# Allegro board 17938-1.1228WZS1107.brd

Outline 227 x 153 mm; copper layers: TOP, L2SGND, L3, L4, L5SGND, BOTTOM. Coordinates in mm from the lower left corner of the outline.

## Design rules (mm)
constraint set DEFAULT: min track width 0.127, pair gap 0.102
net group CFG: nets CFG3 CFG4
net group CNVI_CLK: nets CLKIN_XTAL_LCP PULSAR_38P4M_REFCLK
net group DDR4_A_BA_40-MW: nets M_A_BA0 M_A_BA1
net group DDR4_A_BG_40-MW: nets M_A_BG0 M_A_BG1
net group DDR4_B_BA_40-MW: nets M_B_BA0 M_B_BA1
net group DDR4_B_BG_40-MW: nets M_B_BG0 M_B_BG1
net group DDR4_RST_40: nets DDR4_DRAMRST# SM_DRAMRST#_CPU
net group EMMC: nets EMMC_RESET# EMMC_RST_N
net group ESPI_IO0: nets ESPI_IO0 PCH_ESPI_IO0
net group ESPI_IO1: nets ESPI_IO1 PCH_ESPI_IO1
net group ESPI_IO2: nets ESPI_IO2 PCH_ESPI_IO2
net group ESPI_IO3: nets ESPI_IO3 PCH_ESPI_IO3
net group LED_5MIL: nets AMBER_LED_BAT WHITE_LED_BAT
net group MEM_SMBCLK: nets MEM_SMBCLK PCH_SMBCLK
net group MEM_SMBDATA: nets MEM_SMBDATA PCH_SMBDATA
net group ODD_SATA_RX_CON_N: nets ODD_SATA_RX_N12 SSD_ODD_SATA_RX_N12
net group ODD_SATA_RX_CON_P: nets ODD_SATA_RX_P12 SSD_ODD_SATA_RX_P12
net group ODD_SATA_TX_CON_N: nets ODD_SATA_TX_N12 SSD_ODD_SATA_TX_N12
net group ODD_SATA_TX_CON_P: nets ODD_SATA_TX_P12 SSD_ODD_SATA_TX_P12
net group SPI_HOLD_CPU: nets SPI_HOLD_CPU_R SPI_HOLD_ROM2
net group SPI_WP_CPU: nets SPI_WP_CPU_R SPI_WP_ROM2
net group T8-MW: nets CMP_VIN0 CMP_VIN0_R
net group THERM_SHUTDOWN: nets PURE_HW_SHUTDOWN# THERM_SYS_SHDN#
net group USB4_USB20_CON_N: nets USB4_USB20_CON_N USB4_USB20_N
net group USB4_USB20_CON_P: nets USB4_USB20_CON_P USB4_USB20_P
net group WWAN_USB20_N: nets WWAN_USB20_N WWAN_USB20_N_R
net group WWAN_USB20_P: nets WWAN_USB20_P WWAN_USB20_P_R
net group 00_POWER_4M: nets ACOK_IN_M PSID_DISABLE#_R_C PWR_1D05V_TON PWR_1D8V_EN PWR_1D8V_PG PWR_3D3V_EN PWR_3D3V_EN1 PWR_5V_EN
net group 00_POWER_10M: nets 1D0V_VCCA_XTAL 1D0V_VCCAMPHYPLL 1D0V_VCCDSW 1D8V_S0_CT1 1V_VCCSTG 3D3V_LAN_CT2 3V5V_CT1 3V5V_CT2 CEXT DC_IN_OFF FP_3D3V I_BATT LDO1_CAP LDO2_CAP LDO3_CAP LOM_TCT LPS_SW LPS_SW_A LPS_SW_C LPS_SW_D MESW1_B MIC_CAP NXP3290CAP PD_VBUS_DISCHG_N1 PD_VCCD PS_ID PU4348_G RSET SM_PGCNTL V3D3_STB VCCRTCEXT VDDI
net group 00_POWER_10M_10M: nets PWR_CHG_PHASE2_R
net group 00_POWER_10M_POWER: nets 3D3V_GSEN2 3D3V_MUX 3D3V_MUX2 3D3V_MUX_VCC AC_IN#_G AD_OFF_L AD_OFF_R PWR_1D05V_EN PWR_1D05V_PFM# PWR_1D05V_SS PWR_2D5V_EN PWR_5V_EN1 PWR_5V_VOUT PWR_CHG_ACIN PWR_CHG_ADP/ACIN PWR_CHG_AIN PWR_CHG_AIN_R PWR_CHG_AMON PWR_CHG_ASGATE PWR_CHG_ASGATE/NTC PWR_CHG_BATGONE PWR_CHG_CMRSC PWR_CHG_COMP PWR_CHG_COMP_R PWR_CHG_DCIN PWR_CHG_DCIN_R PWR_CHG_NTC PWR_CHG_OTGEN PWR_CHG_OTGPG PWR_CHG_PROG PWR_CHG_VBAT1 PWR_VCCGT_COMP PWR_VCCGT_COMP1 PWR_VCCGT_FCCM# PWR_VCCGT_FCCM#_RA PWR_VCCGT_FCCM#_RB PWR_VCCGT_IMON PWR_VCCGT_ISEN1 PWR_VCCGT_ISEN2 PWR_VCCGT_ISUMN PWR_VCCGT_ISUMN_P_1 PWR_VCCGT_ISUMN_P_2 PWR_VCCGT_ISUMN_RC PWR_VCCGT_ISUMNB PWR_VCCGT_ISUMP PWR_VCCGT_NTC PWR_VCCGT_NTC1 PWR_VCCGT_PWMA PWR_VCCGT_PWMA_RA PWR_VCCGT_PWMB PWR_VCCGT_PWMB_RA PWR_VCCGT_RTN PWR_VCCSA_COMP PWR_VCCSA_COMP_RC PWR_VCCSA_FCCM PWR_VCCSA_IMON PWR_VCCSA_ISUMN PWR_VCCSA_ISUMN_P_1 PWR_VCCSA_ISUMN_P_2 PWR_VCCSA_ISUMN_RC PWR_VCCSA_ISUMNB PWR_VCCSA_ISUMP PWR_VCCSA_PWM PWR_VCCSA_RTN PWR_VCORE_COMP PWR_VCORE_COMP1 PWR_VCORE_FCCM# PWR_VCORE_FCCM#_R PWR_VCORE_IMON PWR_VCORE_ISUMN PWR_VCORE_ISUMN_P_1 PWR_VCORE_ISUMN_P_2 PWR_VCORE_ISUMN_RC PWR_VCORE_ISUMNA PWR_VCORE_ISUMP PWR_VCORE_NTC PWR_VCORE_NTC1 PWR_VCORE_PROG1 PWR_VCORE_PROG2 PWR_VCORE_PWM PWR_VCORE_PWM_R PWR_VCORE_RTN PWR_VCORE_VR PWR_VCORE_VRHOT# PWR_VDDQ_CS PWR_VDDQ_EN PWR_VDDQ_PG PWR_VDDQ_TON PWR_VDDQ_VTTREF VDD
net group 00_POWER_15M: nets Q6205_Q USBC1_CC1_CONN USBC1_CC2_CONN
net group 00_POWER_15M_20M: nets PWR_1D05V_FB PWR_1D05V_FB_A PWR_1D8V_FB PWR_2D5V_FB PWR_3D3V_FB PWR_5V_FB PWR_5V_FB_A PWR_VCCGT_FB PWR_VCCGT_FB1 PWR_VCCGT_FB2 PWR_VCCGT_FB_RC PWR_VCCSA_FB PWR_VCCSA_FB1 PWR_VCCSA_FB2 PWR_VCCSA_FB_RC PWR_VCORE_FB PWR_VCORE_FB1 PWR_VCORE_FB2 PWR_VCORE_FB_RC PWR_VDDQ_FB
net group 00_POWER_20M: nets 1D8V_AVDD2 1D8V_EMMC 1D24V_VCCDPHY_EC 3D3V_AUX_S5 3D3V_RTC 3D3V_RTC_SYS 3D3V_SPIVCC1 3D3V_VCCPRTC 5V_HDMI 5V_IRLED 5V_VCONN_P1 5V_VCONN_P1_CCG4 +5V_AVDD +5V_KB_BL +RTC_CELL_VBAT +RTC_VCC +V_VREF_PATH1 CPVDD VDD10 VREF_CPU
net group 00_POWER_20M_20M: nets PWR_1D05V_BST PWR_CHG_BGATE PWR_CHG_BOOT1 PWR_CHG_BOOT2 PWR_CHG_BT1_R PWR_CHG_BT2_R PWR_VCCGT_BOOTA PWR_VCCGT_BOOTA_RC PWR_VCCGT_BOOTB PWR_VCCGT_BOOTB_RC PWR_VCCGT_BOOTRA PWR_VCCGT_BOOTRB PWR_VCCGT_SNB1 PWR_VCCGT_SNB2 PWR_VCCGT_VCCDA PWR_VCCGT_VCCDB PWR_VCCSA_BST PWR_VCCSA_BST_RC PWR_VCORE_BOOT PWR_VCORE_BOOT_RC PWR_VCORE_BOOTR PWR_VCORE_SNB PWR_VDDQ_BOOT PWR_VDDQ_BOOTA
net group 00_POWER_20M_POWER: nets PWR_3D3V_BOOT PWR_3D3V_BOOT_A PWR_5V_BOOT PWR_5V_BOOT_A PWR_5V_LDO PWR_CHG_BGATE/HG2 PWR_CHG_BGATE_22 PWR_CHG_BGATE_22_R PWR_CHG_NGATE PWR_CHG_VDDP PWR_VCORE_VCC PWR_VCORE_VCC_R PWR_VCORE_VIN
net group 00_POWER_25M_20M: nets PQ3802_1
net group 00_POWER_30M_10M: nets PWR_CHG_UGATE1
net group 00_POWER_40M: nets 3D3V_CAMERA_S0 3D3V_S5_PCH_R +1.8VALW_EC PQ4348_D
net group 00_POWER_80M: nets 3D3V_LCDVDD_R
net group 00_POWER_100M: nets 5V_AUX_S5
net group 00_POWER_320M_POWER: nets PWR_3D3V_VOUT
net group ASYNCHRONOUS: nets H_CPUPWRGD PROCHOT#_CPU_R PWR_CHG_PROCHOT# PWR_CHG_PROCHOT#_R THERMTRIP#_CPU VCCST_PWRGD_R VDDQ_PWRGD VR_EN XDP_DBRESET#
net group AUDIO_12MIL: nets CPVEE
net group AUDIO_BEEP_10MIL: nets AUD_HPJD_N AUD_PC_BEEP AUD_PC_BEEP_C AUD_SENSE AUD_VREF BEEP CBN CBP HDA_SPKR_R JACK_PLUG JACK_PLUG_DET KBC_BEEP_R LINE1_VREFO LINE1_VREFO_D1 LINE1_VREFO_D2 MIC2_VREFO SPKR
net group AUDIO_BEEP_15MIL: nets AUD_PORTA_L_HPMIC1 AUD_PORTA_R_HPMIC1 LINE1-L_C LINE1-L_R LINE1_L LINE1_R
net group AUDIO_DIGITAL_50-MWS: nets HDA_RST_N_CPU
net group AUDIO_JACK_15MIL: nets AUD_HP1_JACK_L AUD_HP1_JACK_L1 AUD_HP1_JACK_R
net group AUDIO_SLEEVE_40MIL: nets SLEEVE_R
net group BOT_MUX_N: nets USB1_USB20_N
net group BOT_MUX_P: nets USB1_USB20_P
net group BT_USB20_CON_N: nets BT_USB20_N
net group BT_USB20_CON_P: nets BT_USB20_P
net group CARD1_USB20_CON_N: nets CARD1_USB20_N
net group CARD1_USB20_CON_P: nets CARD1_USB20_P
net group CCD_USB20_CON_N: nets CCD_USB20_N
net group CCD_USB20_CON_P: nets CCD_USB20_P
net group CLK_50: nets PD_SWD_CLK SUS_CLK SUSACK#_R SUSCLK_WLAN
net group CLK_ITE8010: nets CLK_ITE8010 CPU_SMB_SCL_THM GPU_THM_SMBCLK SML1_SMBCLK
net group CNV_BRI_DT: nets CNV_BRI_DT
net group CNV_BRI_RSP: nets CNV_BRI_RSP
net group CNV_RGI_DT: nets CNV_RGI_DT
net group CNV_RGI_RSP: nets CNV_RGI_RSP
net group CNVI_RCOMP: nets CNV_WT_RCOMP
net group COMP_20MIL: nets CFG_RCOMP CPU_POPIRCOMP PCH_POPIRCOMP SM_RCOMP_0 SM_RCOMP_1 SM_RCOMP_2
net group CPU_50-MWS: nets CMP_VOUT0
net group CPU_DP1_CTRL_CLK: nets CPU_DP1_CTRL_CLK
net group CPU_DP1_CTRL_DATA: nets CPU_DP1_CTRL_DATA
net group CPU_SMB_SDA_THM: nets CPU_SMB_SDA_THM DAT_ITE8010 GPU_THM_SMBDAT SML1_SMBDATA
net group CRITICAL: nets PCH_RSMRST# PM_RSMRST# PM_RSMRST#_M RESET_OUT# RTC_RST# SIO_PWRBTN# SIO_RCIN# SM_INTRUDER# SRTC_RST# SYS_PWROK
net group CRT_AUX_CPU_N: nets DP2_AUX_C_N DP2_AUX_CPU_N IN_AUX_N TYPEC_DP_AUXN
net group CRT_AUX_CPU_P: nets DP2_AUX_C_P DP2_AUX_CPU_P IN_AUX_P TYPEC_DP_AUXP
net group CRT_DDI_TX_N0: nets CRT_DDI_TX_N0 DP2_DDI_TX_N0 DP2_DDI_TX_R_N0 DP2_DDI_TX_R_N0_R DP2_DDI_TX_RE_C_N0 DP2_DEMUX_OUT2_D0N TYPEC_DP_N0 TYPEC_DP_N0_C
net group CRT_DDI_TX_N1: nets CRT_DDI_TX_N1 DP2_DDI_TX_N1 DP2_DDI_TX_R_N1 DP2_DDI_TX_R_N1_R DP2_DDI_TX_RE_C_N1 DP2_DEMUX_OUT2_D1N TYPEC_DP_N1 TYPEC_DP_N1_C
net group CRT_DDI_TX_P0: nets CRT_DDI_TX_P0 DP2_DDI_TX_P0 DP2_DDI_TX_R_P0 DP2_DDI_TX_R_P0_R DP2_DDI_TX_RE_C_P0 DP2_DEMUX_OUT2_D0P TYPEC_DP_P0 TYPEC_DP_P0_C
net group CRT_DDI_TX_P1: nets CRT_DDI_TX_P1 DP2_DDI_TX_P1 DP2_DDI_TX_R_P1 DP2_DDI_TX_R_P1_R DP2_DDI_TX_RE_C_P1 DP2_DEMUX_OUT2_D1P TYPEC_DP_P1 TYPEC_DP_P1_C
net group DDR4_A_CKE_40-MW: nets M_A_CKE0 M_A_CKE1 M_A_CS#0 M_A_CS#1 M_A_DIMA_ODT0 M_A_DIMA_ODT1
net group DDR4_A_CMD_40-MW: nets M_A_A0 M_A_A1 M_A_A2 M_A_A3 M_A_A4 M_A_A5 M_A_A6 M_A_A7 M_A_A8 M_A_A9 M_A_A10 M_A_A11 M_A_A12 M_A_A13 M_A_A14 M_A_A15 M_A_A16 M_A_ACT_N M_A_ALERT_N M_A_PARITY
net group DDR4_A_DATA_00_50-MW: nets M_A_DQ0 M_A_DQ1 M_A_DQ2 M_A_DQ3 M_A_DQ4 M_A_DQ5 M_A_DQ6 M_A_DQ7
net group DDR4_A_DATA_01_50-MW: nets M_A_DQ8 M_A_DQ9 M_A_DQ10 M_A_DQ11 M_A_DQ12 M_A_DQ13 M_A_DQ14 M_A_DQ15
net group DDR4_A_DATA_02_50-MW: nets M_A_DQ16 M_A_DQ17 M_A_DQ18 M_A_DQ19 M_A_DQ20 M_A_DQ21 M_A_DQ22 M_A_DQ23
net group DDR4_A_DATA_03_50-MW: nets M_A_DQ24 M_A_DQ25 M_A_DQ26 M_A_DQ27 M_A_DQ28 M_A_DQ29 M_A_DQ30 M_A_DQ31
net group DDR4_A_DATA_04_50--MW: nets M_A_DQ32 M_A_DQ33 M_A_DQ34 M_A_DQ35 M_A_DQ36 M_A_DQ37 M_A_DQ38 M_A_DQ39
net group DDR4_A_DATA_05_50-MW: nets M_A_DQ40 M_A_DQ41 M_A_DQ42 M_A_DQ43 M_A_DQ44 M_A_DQ45 M_A_DQ46 M_A_DQ47
net group DDR4_A_DATA_06_50-MW: nets M_A_DQ48 M_A_DQ49 M_A_DQ50 M_A_DQ51 M_A_DQ52 M_A_DQ53 M_A_DQ54 M_A_DQ55
net group DDR4_A_DATA_07_50-MW: nets M_A_DQ56 M_A_DQ57 M_A_DQ58 M_A_DQ59 M_A_DQ60 M_A_DQ61 M_A_DQ62 M_A_DQ63
net group DDR4_B_CKE_40-MW: nets M_B_CKE0 M_B_CKE1 M_B_CS#0 M_B_CS#1 M_B_DIMB_ODT0 M_B_DIMB_ODT1
net group DDR4_B_CMD_40--MW: nets M_B_A0 M_B_A1 M_B_A2 M_B_A3 M_B_A4 M_B_A5 M_B_A6 M_B_A7 M_B_A8 M_B_A9 M_B_A10 M_B_A11 M_B_A12 M_B_A13 M_B_A14 M_B_A15 M_B_A16 M_B_ACT_N M_B_ALERT_N M_B_PARITY
net group DDR4_B_DATA_00_50-MW: nets M_B_DQ0 M_B_DQ1 M_B_DQ2 M_B_DQ3 M_B_DQ4 M_B_DQ5 M_B_DQ6 M_B_DQ7
net group DDR4_B_DATA_01_50-MW: nets M_B_DQ8 M_B_DQ9 M_B_DQ10 M_B_DQ11 M_B_DQ12 M_B_DQ13 M_B_DQ14 M_B_DQ15
net group DDR4_B_DATA_02_50-MW: nets M_B_DQ16 M_B_DQ17 M_B_DQ18 M_B_DQ19 M_B_DQ20 M_B_DQ21 M_B_DQ22 M_B_DQ23
net group DDR4_B_DATA_03_50-MW: nets M_B_DQ24 M_B_DQ25 M_B_DQ26 M_B_DQ27 M_B_DQ28 M_B_DQ29 M_B_DQ30 M_B_DQ31
net group DDR4_B_DATA_04_50-MW: nets M_B_DQ32 M_B_DQ33 M_B_DQ34 M_B_DQ35 M_B_DQ36 M_B_DQ37 M_B_DQ38 M_B_DQ39
net group DDR4_B_DATA_05_50-MW: nets M_B_DQ40 M_B_DQ41 M_B_DQ42 M_B_DQ43 M_B_DQ44 M_B_DQ45 M_B_DQ46 M_B_DQ47
net group DDR4_B_DATA_06_50-MW: nets M_B_DQ48 M_B_DQ49 M_B_DQ50 M_B_DQ51 M_B_DQ52 M_B_DQ53 M_B_DQ54 M_B_DQ55
net group DDR4_B_DATA_07_50-MW: nets M_B_DQ56 M_B_DQ57 M_B_DQ58 M_B_DQ59 M_B_DQ60 M_B_DQ61 M_B_DQ62 M_B_DQ63
net group DDR4_VREF_40: nets V_SM_VREF_CNTB
net group DMIC: nets DMIC_CLK_EDP DMIC_DATA_EDP DMIC_SCL_CODEC DMIC_SCL_CODEC_R DMIC_SDA_CODEC
net group DP2_DDI_TX_C_N2: nets DP2_DDI_TX_C_N2_R DP2_DDI_TX_RE_C_N2 TYPEC_DP_N2 TYPEC_DP_N2_C
net group DP2_DDI_TX_C_N3: nets DP2_DDI_TX_C_N3_R DP2_DDI_TX_RE_C_N3 TYPEC_DP_N3 TYPEC_DP_N3_C
net group DP2_DDI_TX_C_P2: nets DP2_DDI_TX_C_P2_R DP2_DDI_TX_RE_C_P2 TYPEC_DP_P2 TYPEC_DP_P2_C
net group DP2_DDI_TX_C_P3: nets DP2_DDI_TX_C_P3_R DP2_DDI_TX_RE_C_P3 TYPEC_DP_P3 TYPEC_DP_P3_C
net group E3: nets 3D3V_LCDVDD_R_C 3D3V_LCDVDD_S0_C 3D3V_S0_C 3D3V_SSD_C BT_PWR_IN+ BT_PWR_IN- DCBATOUT_C1 DCBATOUT_C6 DCBATOUT_C7 DCBATOUT_C8 DCBATOUT_LCD_C DCBATOUT_LCD_R_C PWR_DCBATOUT_VCCGTA_C PWR_DCBATOUT_VCCSA_C PWR_DCBATOUT_VCORE_C PWR_DCBATOUT_VDDQ_C
net group EDP_AUX_CON_N: nets EDP_AUX_CPU_N
net group EDP_AUX_CON_P: nets EDP_AUX_CPU_P
net group EDP_RCOMP: nets EDP_RCOMP_CPU
net group EDP_TX_CON_N0: nets EDP_TX_CPU_N0
net group EDP_TX_CON_N1: nets EDP_TX_CPU_N1
net group EDP_TX_CON_P0: nets EDP_TX_CPU_P0
net group EDP_TX_CON_P1: nets EDP_TX_CPU_P1
net group EMMC_CLK: nets EMMC_CLK
net group EMMC_CMD: nets EMMC_CMD
net group EMMC_D0: nets EMMC_D0
net group EMMC_D1: nets EMMC_D1
net group EMMC_D2: nets EMMC_D2
net group EMMC_D3: nets EMMC_D3
net group EMMC_D4: nets EMMC_D4
net group EMMC_D5: nets EMMC_D5
net group EMMC_D6: nets EMMC_D6
net group EMMC_D7: nets EMMC_D7
net group EMMC_RCLK: nets EMMC_RCLK
net group EMMC_RCOMP: nets SD_RCOMP
net group EPSI_50: nets ESPI_ALERT#
net group ESPI_CLK: nets PCH_ESPI_CLK
net group FAN_TACH: nets FAN1_TACH FAN_TACH1 FAN_TACH1_C
net group FP1_USB20_CON_N: nets FP1_USB20_N
net group FP1_USB20_CON_P: nets FP1_USB20_P
net group GND: nets U9101_2_GND
net group HDD2_SATA_RX_CON_N: nets HDD_SATA_RX_N11
net group HDD2_SATA_RX_CON_P: nets HDD_SATA_RX_P11
net group HDD2_SATA_TX_CON_N: nets HDD_SATA_TX_N11
net group HDD2_SATA_TX_CON_P: nets HDD_SATA_TX_P11
net group HDMI_DDI_TX_CMC_N0: nets HDMI_DDI_TX_N2
net group HDMI_DDI_TX_CMC_N1: nets HDMI_DDI_TX_N1
net group HDMI_DDI_TX_CMC_N2: nets HDMI_DDI_TX_N0
net group HDMI_DDI_TX_CMC_N3: nets HDMI_DDI_TX_N3
net group HDMI_DDI_TX_CMC_P0: nets HDMI_DDI_TX_P2
net group HDMI_DDI_TX_CMC_P1: nets HDMI_DDI_TX_P1
net group HDMI_DDI_TX_CMC_P2: nets HDMI_DDI_TX_P0
net group HDMI_DDI_TX_CMC_P3: nets HDMI_DDI_TX_P3
net group JTAG-MW: nets PCH_JTAG_TCK PCH_JTAG_TDI PCH_JTAG_TDO PCH_JTAG_TMS
net group KB: nets KSI0 KSI1 KSI2 KSI3 KSI4 KSI5 KSI6 KSI7 KSO0 KSO1 KSO2 KSO3 KSO4 KSO5 KSO6 KSO7 KSO8 KSO9 KSO10 KSO11 KSO12 KSO13 KSO14 KSO15 KSO16
net group LAN_MDI0_N: nets MDO0-
net group LAN_MDI0_P: nets MDO0+
net group LAN_MDI1_N: nets MDO1-
net group LAN_MDI1_P: nets MDO1+
net group LAN_MDI2_N: nets MDO2-
net group LAN_MDI2_P: nets MDO2+
net group LAN_MDI3_N: nets MDO3-
net group LAN_MDI3_P: nets MDO3+
net group LAN_PCIE_RX_C_N: nets LAN_PCIE_RX_N
net group LAN_PCIE_RX_C_P: nets LAN_PCIE_RX_P
net group LED: nets BAT1_LED# BAT2_LED# BATT_WHITE_LED# BATT_WHITE_LED#_Q CAP_LED# CAP_LED#_R CHG_AMBER_LED# CHG_AMBER_LED#_Q M2_PCIE_LED# MASK_SATA_LED# PWR_LED# Q6407_B Q6407_C SATA_LED# SATA_LED#_D SYS_LED_MASK#
net group LED_8MIL: nets BAT_AMBER BAT_WHITE CAP_LED CAP_LED_Q LAN_LED0 LAN_LED0_Q LAN_LED0_R PWR_LED#_C PWR_LED#_R
net group OHTER_3D5MIL: nets 3V_5V_EN 3V_5V_POK AD_IA AUX_EN_WOWL AUX_EN_WOWL_R BLUETOOTH_EN BMON22 CAM_EN CLK_PCIE_LAN_REQ# CLK_PCIE_NVME_REQ# CLK_PCIE_WLAN_REQ# CNVI_EN# CPU_DP1_HPD CPU_DP_HPD_R CRT_DP_HPD_R DP2_HPD_CPU ESPI_CLK_CON ESPI_CS#_CON ESPI_IO0_CON ESPI_IO1_CON ESPI_IO2_CON ESPI_IO3_CON ESPI_RST#_CON FPR_SCAN# GPP_H1_SFRM GPP_H2_CLKREQ0 GPPC_H18_VCCIO_LPM HW_ACAV_IN IR_CAM_DET# KB_DET# KB_LED_BL_DET KBC_PWRBTN# L_BKLT_EN LAN_WAKE# LCD_CBL_DET# LCD_TST LCD_VCC_TEST_EN LID_CL_SIO# LID_CLOSE#_C M2_SSD_PEDET PANEL_BKEN PANEL_MONITOR PBAT_PRES# PCIE_WAKE# PD4403_K PLTRST#_CPU PQ4405_2 PQ4408_C PROCHOT#_CPU PTP_DIS# PWR_BD_DET# PWR_LED#_Q SIO_EXT_WAKE# SIO_SLP_S0# SIO_SLP_S4# SMB_ALERT# SSD_DEVSLP SSD_DEVSLP_R TOUCH_I2C_DET# TOUCH_PANEL_INTR# TP_EN# TP_WAKE_KBC# USB_EN# USB_OC0# USB_OC1# VGA_DB_DET# VRAM_ID1 VRAM_ID2 WIFI_RF_EN WWAN_BB_RST# WWAN_CLKREQ_CPU_N WWAN_DB_DET# WWAN_DB_DET#_R WWAN_GPIO_PERST# WWAN_PCIE_WAKE_N
net group OTHER_4MIL: nets 3D3V_CAMERA_CT1 3D3V_TP_CT2 3V_5V_POK# 5V_VCONN_EN 20V_VCCPD_VBUS_R +SDC_IN_SW_R1 ACOK# ALERT# AUX_ON BKLT_IN_EC BLON_OUT_C BLUETOOTH_EN_R BOARD_ID BOARD_ID1 BREATH_LED# BT_PCMFRM_RSTN BT_PCMOUT_CLKREQ0 C10_GATE CAD_SNK_MUX CCG4_FLIP# CCG4_I2C_INT# CCG4_ID_1 CFG0 CFG0_DP_MUX CFG1 CFG19 CHGR_PSYS_IMVP CLK_PCIE_SD_REQ# CPU_DP2_HPD CPU_DP_HPD_MUX CRT_DP_HPD CTL1 CTL2 CTL3 DBC_EN_R DBC_PANEL_EN DCBATOUT_LCD_PG DCBATOUT_LCD_PWRGD DOCK_USB_EN_A DOCK_USB_EN_B DPEQ0_A1 DPEQ1 EC_D_INHIB EDP_DISP_UTIL EDP_FHD_DET# EDP_FHD_DET#_R EDP_HPD EDP_HPD_CONN EQ0 EQ1 EXT_PWR_GATE# FALL_INT2 FFS_INT1 FFS_INT2 FFS_INT2_Q FLT_NXP3290 FP_EN# GPD11/LANPHYPC GPD_7 GPP_H21 GPP_H23 GSENSOR_CS GSENSOR_SDO HDD_DET# HDD_DEVSLP_R HDMI_HPD_B HDMI_HPD_CON HOST_DEBUG_TX HOST_DEBUG_TX_CON HPDIN HW_ACAV_IN0 HW_ACAVIN_NB0 I2C_CTL_EN I2CEN I_ADP IC_DELAY ICSP_CLR ILIM_HI ILIM_LO ILIM_SEL INPUT3VSEL INT#_ITE8010 IO_DB_DET# IO_DB_DET#_EC IO_DB_DET#_GPPG5 IO_DB_DET#_R ISOLATE# IST_TRIG ITP_PMODE JIO3_PCIE_WAKE# KB_BL_CTRL# KB_LED_DET_C KB_LED_PWM KBC_PWRBTN#_C L_BKLT_EN_L LAN_CABLE_DETECT_R_# LANWAKE# LCD_TST_C LCDVDD_EN LCDVDD_PG LCDVDD_PWRGD LOM_CABLE_DETECT# LPS_SW_R MCT0 MCT1 MCT2 MCT3 ME_FWP ME_FWP_R MODEL_ID MSATA_DEVSLP_R MUX_HPD_PD MUX_SAI MUX_SAO MUX_SBI MUX_SBO NB_MUTE# NRB_BIT NUVOTON_PP NXP3290_FO NXP3290_ILIM OUT1_CA_DET OUT2_CA_DET PANEL_BKEN_EC PANEL_PWRGD_R PBAT_PRES1# PC10 PC11 PC20 PC21 PCH_BATLOW# PCH_PLTRST# PCH_TPAN_VDD_EN PCH_WAKE# PCIE_LAN_WAKE# PD4403_A PD_VBUS_C_CTRL1_A PD_VBUS_C_CTRL1_R PD_VBUS_C_EN_A PD_VBUS_C_EN_B PD_XRES PDB_R PEQ PLTRST#_CPU_D PLTRST#_CPU_G PM_LAN_ENABLE POWER_SW_IN# PQ4405_3 PQ4405_5 PQ4405_6 PQ4408_E PQ4417_D PQ4417_G PQ4418_2 PQ4418_3 PQ4418_5 PQ4418_6 PRIM_PWRGD PROCHOT PROJECT_ID0 PROJECT_ID1 PROJECT_ID2 PROJECT_ID3 PS_ID_R PS_ID_R1 PWR_CHG_ACOK PWR_CHG_PSYS Q501_G Q2510_G Q5503_B Q5503_C Q5503_E Q5504_B Q5504_C Q5505_E Q9301_G REXT1 RTC_DET# RUNPWROK SA0_CHA_DIM0 SA0_CHB_DIM0 SA1_CHA_DIM0 SA1_CHB_DIM0 SA2_CHA_DIM0 SA2_CHB_DIM0 SATA1_ODD_PRSNT# SATA_ODD_DA#_C SATA_ODD_PRSNT#_R SD_READ_MODE# SD_READ_MODE#_R SIO_EXT_SMI# SIO_SLP_A# SIO_SLP_S3# SIO_SLP_S5# SM_PGCNTL_Q SSD2_DEVSLP SSD_SCP# SSEQ0_A0 SSEQ1 ST_GPIO ST_PP SW_PIN SYS_PRES1# SYSPWR_PRES T_CRIT# TOUCH_PAD_INTR# TOUCH_PANEL_PD# TOUCH_REPORT_SW TPAN_VDD_EN_R TPM_GPIO1 TPM_GPIO4 TPM_ID TPM_SPI_IRQ# TPS2544_FAULT# TPS70933_EN TPS70933_EN_G TS#_DIMM0_1 TS#_DIMM1_1 TS_INT# TYPEC_DCIN1_EN# USB2_ID USB2_VBUSSENSE USB_OC1#_R USB_OC2# USB_OC3# USB_PWR_SHR_EN_L# V0.85A_VID0 V0.85A_VID1 VBUS_P_CTRL VBUS_P_CTRL_R VCCDSW_ON VCCPD_VBUS_ACK VCCSTG_EN_R1 VCCSTU_EN_R VCI_IN1# VCREF0 VR_RDY VRALERT# WIFI_RF_EN_R WLAN_EN# WWAN_FULL_PWR_EN WWAN_FULL_PWR_EN_D8 WWAN_FULL_PWR_EN_R
net group PCIE_RCOMP: nets PCIE_RCOMPN PCIE_RCOMPP USBCOMP
net group PLATFORM: nets 1D05V_S5_PWRGD 3V_5V_DSW_OK AC_DIS AC_PRESENT ALWON CNVI_EN#_R EDP_VDD_EN GPP_E23_STRAP HDD_DEVSLP HW_ACAVIN_NB ME_SUS_PWR_ACK_R NC_AUX_EN_WOWL_EC PD_VBUS_C_CTRL1 PD_VBUS_DISCHG PIRQA# PWR_2D5V_PG RSMRST_PWRGD# RTC_3P3_EN_G RTCRST_ON TP_ON#_GATE TPM_GPIO0 USB_POWERSHARE_VBUS_EN
net group PWM: nets BKLT_CTRL FAN1_PWM FAN_PWM1_C L_BKLT_CTRL LCD_BRIGHTNESS
net group REF10M: nets VR_CAP
net group SIGNAL_SVID: nets SVID_ALERT#_CPU SVID_ALERT#_CPU_R SVID_ALERT#_VR SVID_CLK_CPU_R SVID_CLK_VR SVID_DATA_CPU_R SVID_DATA_VR
net group SIGNAL_V_F_5MIL: nets XCLK_BIASREF
net group SMBUS: nets CCG4_I2C_SCL CCG4_I2C_SDA CLK_TP_SIO CPU_DP2_CTRL_CLK CPU_DP2_CTRL_DATA DAT_TP_SIO DMIC_PCH_CLK DMIC_PCH_DATA HDMI_SCL_R HDMI_SDA_R I2C0_SCL_TCH_PAD I2C0_SCL_TCH_PNL I2C0_SDA_TCH_PAD I2C0_SDA_TCH_PNL I2C1_SCL_R I2C1_SDA_R I2C_CLK I2C_CLK_PD I2C_CLK_PD_MUX I2C_DATA_PD I2C_DATA_PD_MUX I2C_SDA ICSP_CLK ICSP_DAT PBAT_CHG_SMBCLK PBAT_CHG_SMBDAT PBAT_SMBCLK1 PBAT_SMBDAT1 PMBD_SCL_R PMBD_SDA_R SML0_ALERT# SML0_SMBCLK SML0_SMBDATA SML1ALERT# TPCLK_C TPDATA_C TYPEC_SMBCLK TYPEC_SMBDA
net group SPI_50-MWS: nets SPI_CS2#_IC SPI_CS_CPU_N0 SPI_CS_CPU_N1 SPI_CS_CPU_N2 SPI_IRQ#_TPM2
net group SPI_CLK_CPU: nets SPI_CLK_CPU_R SPI_CLK_ROM SPI_CLK_ROM2 SPI_CLK_ROM_TPM
net group SPI_SI_CPU: nets SPI_SI_CPU_R SPI_SI_ROM2 SPI_SI_ROM_TPM
net group SPI_SO_CPU: nets SPI_SO_CPU_R SPI_SO_ROM2 SPI_SO_ROM_TPM
net group SSD_PCIE_TX_CON_N13: nets SSD_PCIE_TX_N13
net group SSD_PCIE_TX_CON_N14: nets SSD_PCIE_TX_N14
net group SSD_PCIE_TX_CON_N15: nets SSD_PCIE_TX_N15
net group SSD_PCIE_TX_CON_P13: nets SSD_PCIE_TX_P13
net group SSD_PCIE_TX_CON_P14: nets SSD_PCIE_TX_P14
net group SSD_PCIE_TX_CON_P15: nets SSD_PCIE_TX_P15
net group SSD_PCIE_TX_N16: nets SSD_PCIE_TX_N16
net group SSD_PCIE_TX_P16: nets SSD_PCIE_TX_P16
net group SVID_PECI_THERMTRIP: nets H_PECI PECI_CPU SVID_CLK_CPU SVID_DATA_CPU
net group TOUCH_USB20_N: nets TOUCH_USB20_N
net group TOUCH_USB20_P: nets TOUCH_USB20_P
net group UART_MW-MW: nets UART_2_CRXD_DTXD UART_2_CRXD_DTXD_CON UART_2_CTXD_DRXD UART_2_CTXD_DRXD_CON
net group USB1_SSRX_CMC_N1: nets USB1_SSRX_C_N1
net group USB1_SSRX_CMC_N2: nets USB1_SSRX_C_N2
net group USB1_SSRX_CMC_P1: nets USB1_SSRX_C_P1
net group USB1_SSRX_CMC_P2: nets USB1_SSRX_C_P2
net group USB1_SSTX_CMC_N1: nets USB1_SSTX_C_N1
net group USB1_SSTX_CMC_N2: nets USB1_SSTX_C_N2
net group USB1_SSTX_CMC_P1: nets USB1_SSTX_C_P1
net group USB1_SSTX_CMC_P2: nets USB1_SSTX_C_P2
net group USB2_USB20_N: nets USB2_USB20_N
net group USB2_USB20_P: nets USB2_USB20_P
net group USB3_CHAR_2544_N: nets USB3_USB20_N
net group USB3_CHAR_2544_P: nets USB3_USB20_P
net group USB3_USB30_RX_CON_N: nets USB3_USB31_RX_N
net group USB3_USB30_RX_CON_P: nets USB3_USB31_RX_P
net group USB3_USB30_TX_CMC_N: nets USB3_USB31_TX_N
net group USB3_USB30_TX_CMC_P: nets USB3_USB31_TX_P
net group USB4_USB30_RX_C_N: nets USB4_USB30_RX_C_N USB4_USB30_RX_C_R_N USB4_USB30_RX_N
net group USB4_USB30_RX_C_P: nets USB4_USB30_RX_C_P USB4_USB30_RX_C_R_P USB4_USB30_RX_P
net group USB4_USB30_RX_CON_N: nets USB4_USB31_RX_N
net group USB4_USB30_RX_CON_P: nets USB4_USB31_RX_P
net group USB4_USB30_TX_C_N: nets USB4_USB30_TX_C_N USB4_USB30_TX_C_R_N USB4_USB30_TX_N
net group USB4_USB30_TX_C_P: nets USB4_USB30_TX_C_P USB4_USB30_TX_C_R_P USB4_USB30_TX_P
net group USB4_USB30_TX_CMC_N: nets USB4_USB31_TX_N
net group USB4_USB30_TX_CMC_P: nets USB4_USB31_TX_P
net group WWAN_PCIE_TX_N: nets WWAN_PCIE_TX_N
net group WWAN_PCIE_TX_P: nets WWAN_PCIE_TX_P
net group XDP: nets XDP_TCK_JTAGX XDP_TCLK XDP_TDI XDP_TDO_CPU XDP_TMS XDP_TRST#
net group XTAL-MW: nets LANXIN LANXOUT MEC_XTAL1_R MEC_XTAL2 XTL_32K_X1_CPU XTL_32K_X2_CPU
net group XTL_24M: nets XTL_24M_X1_CPU XTL_24M_X1_R XTL_24M_X2_CPU XTL_24M_X2_R
nets with their own width: min track width 0.381; nets GND

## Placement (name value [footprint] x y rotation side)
AFTP1201  AFTE14P-GP  [AFTE14P-75]  196.32 57.13 0 top
AFTP1202  AFTE14P-GP  [AFTE14P-75]  198.25 57.08 0 top
AFTP2601  AFTE14P-GP  [AFTE14P-75]  160.81 86.92 90 top
AFTP2602  AFTE14P-GP  [AFTE14P-75]  161.29 85.07 90 top
AFTP2603  AFTE14P-GP  [AFTE14P-75]  159.72 90.27 90 top
AFTP2604  AFTE14P-GP  [AFTE14P-75]  161.04 88.85 90 top
AFTP2901  AFTE14P-GP  [AFTE14P-75]  14.73 4.47 90 top
AFTP2902  AFTE14P-GP  [AFTE14P-75]  13.14 6.96 180 top
AFTP2903  AFTE14P-GP  [AFTE14P-75]  11.95 4.37 180 top
AFTP2904  AFTE14P-GP  [AFTE14P-75]  11.91 2.37 90 top
AFTP3201  AFTE14P-GP  [AFTE14P-75]  23.52 86.64 0 bottom
AFTP3202  AFTE14P-GP  [AFTE14P-75]  26.37 81.26 0 bottom
AFTP3204  AFTE14P-GP  [AFTE14P-75]  24.69 88.55 0 bottom
AFTP3205  AFTE14P-GP  [AFTE14P-75]  26.47 84.71 180 top
AFTP3206  AFTE14P-GP  [AFTE14P-75]  26.24 82.25 180 top
AFTP3207  AFTE14P-GP  [AFTE14P-75]  19.28 79.78 180 top
AFTP3208  AFTE14P-GP  [AFTE14P-75]  24.46 81.19 0 bottom
AFTP3209  AFTE14P-GP  [AFTE14P-75]  18.63 77.97 180 top
AFTP3502  AFTE14P-GP  [AFTE14P-75]  16.55 47.63 90 top
AFTP3503  AFTE14P-GP  [AFTE14P-75]  16.49 49.54 90 top
AFTP3505  AFTE14P-GP  [AFTE14P-75]  17.73 46.13 90 top
AFTP3506  AFTE14P-GP  [AFTE14P-75]  16.36 44.73 90 top
AFTP3507  AFTE14P-GP  [AFTE14P-75]  18.24 44.22 0 top
AFTP3508  AFTE14P-GP  [AFTE14P-75]  18.55 34.67 0 top
AFTP4001  AFTE14P-GP  [AFTE14P-75]  63.2 121.08 0 top
AFTP4002  AFTE14P-GP  [AFTE14P-75]  58.04 130.46 0 top
AFTP4003  AFTE14P-GP  [AFTE14P-75]  70.75 37.01 0 top
AFTP4302  AFTE14P-GP  [AFTE14P-75]  17.18 124.81 0 top
AFTP4303  AFTE14P-GP  [AFTE14P-75]  21.99 124.93 180 top
AFTP4304  AFTE14P-GP  [AFTE14P-75]  19.46 125.39 90 top
AFTP4306  AFTE14P-GP  [AFTE14P-75]  169.2 33.46 0 top
AFTP4307  AFTE14P-GP  [AFTE14P-75]  133.1 35.13 0 top
AFTP4308  AFTE14P-GP  [AFTE14P-75]  133.15 37.06 180 top
AFTP4309  AFTE14P-GP  [AFTE14P-75]  139.7 34.47 180 top
AFTP4310  AFTE14P-GP  [AFTE14P-75]  140.64 36.93 180 top
AFTP4311  AFTE14P-GP  [AFTE14P-75]  142.57 36.7 180 top
AFTP4312  AFTE14P-GP  [AFTE14P-75]  144.53 36.63 0 top
AFTP4313  AFTE14P-GP  [AFTE14P-75]  152.2 32.74 0 top
AFTP4314  AFTE14P-GP  [AFTE14P-75]  150.28 32.79 0 top
AFTP4315  AFTE14P-GP  [AFTE14P-75]  137.8 34.34 180 top
AFTP4401  AFTE14P-GP  [AFTE14P-75]  174.77 36.5 0 top
AFTP4402  AFTE14P-GP  [AFTE14P-75]  160.44 31.98 0 top
AFTP4403  AFTE14P-GP  [AFTE14P-75]  177.62 46.96 0 top
AFTP4404  AFTE14P-GP  [AFTE14P-75]  194.48 48.43 0 top
AFTP4405  AFTE14P-GP  [AFTE14P-75]  184.81 44.87 0 top
AFTP4406  AFTE14P-GP  [AFTE14P-75]  187.81 45.24 0 top
AFTP4407  AFTE14P-GP  [AFTE14P-75]  123.43 37.85 0 top
AFTP4408  AFTE14P-GP  [AFTE14P-75]  196.68 52.62 0 top
AFTP4501  AFTE14P-GP  [AFTE14P-75]  27.58 35.93 0 top
AFTP4502  AFTE14P-GP  [AFTE14P-75]  64.4 127.99 0 top
AFTP4601  AFTE14P-GP  [AFTE14P-75]  128.53 134.19 0 top
AFTP4602  AFTE14P-GP  [AFTE14P-75]  127.46 135.82 0 top
AFTP4603  AFTE14P-GP  [AFTE14P-75]  100.56 130.36 0 top
AFTP4604  AFTE14P-GP  [AFTE14P-75]  142.79 136.94 0 top
AFTP4605  AFTE14P-GP  [AFTE14P-75]  111.74 131.34 0 top
AFTP4606  AFTE14P-GP  [AFTE14P-75]  113.21 132.57 0 top
AFTP5001  AFTE14P-GP  [AFTE14P-75]  105.79 142.07 180 bottom
AFTP5503  AFTE14P-GP  [AFTE14P-75]  205.88 38.25 0 top
AFTP5504  AFTE14P-GP  [AFTE14P-75]  212.35 50.29 0 top
AFTP5505  AFTE14P-GP  [AFTE14P-75]  183.54 34.04 0 top
AFTP5506  AFTE14P-GP  [AFTE14P-75]  209.89 50.64 0 top
AFTP5509  AFTE14P-GP  [AFTE14P-75]  34.65 31.35 0 top
AFTP5510  AFTE14P-GP  [AFTE14P-75]  32.72 31.42 0 top
AFTP5511  AFTE14P-GP  [AFTE14P-75]  213.16 48.41 0 top
AFTP5514  AFTE14P-GP  [AFTE14P-75]  136.75 35.97 0 top
AFTP5517  AFTE14P-GP  [AFTE14P-75]  215.75 45.42 180 bottom
AFTP5518  AFTE14P-GP  [AFTE14P-75]  217.35 42.8 0 top
AFTP5519  AFTE14P-GP  [AFTE14P-75]  225.45 37.75 0 top
AFTP5520  AFTE14P-GP  [AFTE14P-75]  222.99 38.86 0 top
AFTP5521  AFTE14P-GP  [AFTE14P-75]  220.87 38.72 0 top
AFTP5522  AFTE14P-GP  [AFTE14P-75]  215.19 41.73 0 top
AFTP5523  AFTE14P-GP  [AFTE14P-75]  152.68 137.26 0 top
AFTP5524  AFTE14P-GP  [AFTE14P-75]  218.72 39.7 0 top
AFTP5525  AFTE14P-GP  [AFTE14P-75]  214.91 39.83 0 top
AFTP5526  AFTE14P-GP  [AFTE14P-75]  213.08 40.35 0 top
AFTP5601  AFTE14P-GP  [AFTE14P-75]  197.39 62 0 top
AFTP5602  AFTE14P-GP  [AFTE14P-75]  198.28 60.3 0 top
AFTP6001  AFTE14P-GP  [AFTE14P-75]  190.35 42.37 0 top
AFTP6002  AFTE14P-GP  [AFTE14P-75]  189 40.9 0 top
AFTP6003  AFTE14P-GP  [AFTE14P-75]  187.23 39.14 0 top
AFTP6004  AFTE14P-GP  [AFTE14P-75]  186.32 40.85 0 top
AFTP6005  AFTE14P-GP  [AFTE14P-75]  189.56 37.42 0 top
AFTP6006  AFTE14P-GP  [AFTE14P-75]  188.85 35.43 0 top
AFTP6007  AFTE14P-GP  [AFTE14P-75]  185.04 35.28 0 top
AFTP6108  AFTE14P-GP  [AFTE14P-75]  43.46 101.75 180 top
AFTP6109  AFTE14P-GP  [AFTE14P-75]  42.93 95.97 0 top
AFTP6110  AFTE14P-GP  [AFTE14P-75]  46.23 101.78 180 top
AFTP6111  AFTE14P-GP  [AFTE14P-75]  29.75 97.74 0 top
AFTP6112  AFTE14P-GP  [AFTE14P-75]  41.97 103.77 180 top
AFTP6113  AFTE14P-GP  [AFTE14P-75]  47.37 103.91 90 top
AFTP6114  AFTE14P-GP  [AFTE14P-75]  30.13 95.86 0 top
AFTP6115  AFTE14P-GP  [AFTE14P-75]  42.93 94.06 180 top
AFTP6401  AFTE14P-GP  [AFTE14P-75]  210.29 59.29 270 top
AFTP6402  AFTE14P-GP  [AFTE14P-75]  212.54 62.75 0 top
AFTP6403  AFTE14P-GP  [AFTE14P-75]  195.86 65.41 270 top
AFTP6404  AFTE14P-GP  [AFTE14P-75]  208.37 59.36 270 top
AFTP6407  AFTE14P-GP  [AFTE14P-75]  212.68 57.96 0 top
AFTP6408  AFTE14P-GP  [AFTE14P-75]  212.45 60.83 0 top
AFTP6501  AFTE14P-GP  [AFTE14P-75]  89.69 34.34 0 top
AFTP6524  AFTE14P-GP  [AFTE14P-75]  105.24 32.59 180 top
AFTP6525  AFTE14P-GP  [AFTE14P-75]  107.17 35.85 0 top
AFTP6526  AFTE14P-GP  [AFTE14P-75]  104.52 35.08 0 top
AFTP6527  AFTE14P-GP  [AFTE14P-75]  108.77 33.99 0 top
AFTP6528  AFTE14P-GP  [AFTE14P-75]  106.43 34.09 0 top
AFTP6529  AFTE14P-GP  [AFTE14P-75]  101.73 28.75 0 top
AFTP6530  AFTE14P-GP  [AFTE14P-75]  102.62 34.09 0 top
AFTP6531  AFTE14P-GP  [AFTE14P-75]  74.81 35.69 180 top
AFTP6537  AFTE14P-GP  [AFTE14P-75]  194.28 32.86 0 top
AFTP6541  AFTE14P-GP  [AFTE14P-75]  75.64 33.94 0 top
AFTP6542  AFTE14P-GP  [AFTE14P-75]  56.75 29.57 0 top
AFTP6543  AFTE14P-GP  [AFTE14P-75]  57.94 31.12 0 top
AFTP6544  AFTE14P-GP  [AFTE14P-75]  58.91 32.79 0 top
AFTP6545  AFTE14P-GP  [AFTE14P-75]  59.9 31.12 0 top
AFTP6546  AFTE14P-GP  [AFTE14P-75]  59.9 34.44 0 top
AFTP6547  AFTE14P-GP  [AFTE14P-75]  60.91 32.74 0 top
AFTP6548  AFTE14P-GP  [AFTE14P-75]  61.95 31.12 0 top
AFTP6549  AFTE14P-GP  [AFTE14P-75]  62.87 32.79 0 top
AFTP6550  AFTE14P-GP  [AFTE14P-75]  61.83 34.57 0 top
AFTP6551  AFTE14P-GP  [AFTE14P-75]  63.88 31.14 0 top
AFTP6552  AFTE14P-GP  [AFTE14P-75]  65.05 32.69 0 top
AFTP6553  AFTE14P-GP  [AFTE14P-75]  64.67 34.67 0 top
AFTP6554  AFTE14P-GP  [AFTE14P-75]  66.25 31.14 0 top
AFTP6555  AFTE14P-GP  [AFTE14P-75]  67.21 32.79 0 top
AFTP6556  AFTE14P-GP  [AFTE14P-75]  69.5 32.69 0 top
AFTP6557  AFTE14P-GP  [AFTE14P-75]  73.08 31.17 0 top
AFTP6558  AFTE14P-GP  [AFTE14P-75]  68.28 31.19 0 top
AFTP6559  AFTE14P-GP  [AFTE14P-75]  67.87 34.61 0 top
AFTP6560  AFTE14P-GP  [AFTE14P-75]  70.74 31.24 0 top
AFTP6561  AFTE14P-GP  [AFTE14P-75]  69.79 34.59 0 top
AFTP6562  AFTE14P-GP  [AFTE14P-75]  72.06 32.82 0 top
AFTP6563  AFTE14P-GP  [AFTE14P-75]  74.02 32.84 0 top
AFTP6564  AFTE14P-GP  [AFTE14P-75]  71.71 34.7 0 top
AFTP6565  AFTE14P-GP  [AFTE14P-75]  75.01 31.19 0 top
AFTP6566  AFTE14P-GP  [AFTE14P-75]  75.97 29.54 0 top
AFTP6567  AFTE14P-GP  [AFTE14P-75]  56.66 35.05 0 top
AFTP6607  AFTE14P-GP  [AFTE14P-75]  206.47 40.33 0 top
AFTP6608  AFTE14P-GP  [AFTE14P-75]  205.74 42.1 0 top
AFTP6609  AFTE14P-GP  [AFTE14P-75]  126.27 99.9 0 top
AFTP6610  AFTE14P-GP  [AFTE14P-75]  193.83 41.94 0 top
AFTP6614  AFTE14P-GP  [AFTE14P-75]  197.31 40.21 0 top
AFTP6615  AFTE14P-GP  [AFTE14P-75]  142.5 110.86 0 top
AFTP6801  AFTE14P-GP  [AFTE14P-75]  17.22 31.4 0 top
AFTP6802  AFTE14P-GP  [AFTE14P-75]  16.41 41.23 0 top
AFTP6803  AFTE14P-GP  [AFTE14P-75]  16.84 38.38 0 top
AFTP7101  AFTE14P-GP  [AFTE14P-75]  16.08 118.37 0 top
AFTP7102  AFTE14P-GP  [AFTE14P-75]  15.68 112.69 0 top
AFTP7301  AFTE14P-GP  [AFTE14P-75]  46.88 127.8 0 top
AFTP7302  AFTE14P-GP  [AFTE14P-75]  10.53 115.89 0 top
AFTP7303  AFTE14P-GP  [AFTE14P-75]  9.72 121.59 0 top
AFTP7304  AFTE14P-GP  [AFTE14P-75]  12.53 116.84 0 top
BATT1  ACES-CON10-10-GP-U  [88231-1001-LP]  139.7 34 180 bottom
BIOS1  MX25L12872FM2I-10G-GP  [SOIC8-1H86]  153.07 89.58 180 bottom
BIOS2  MX25L6473FM2I-08G-GP  [SOIC8-1H86]  156.92 105.31 135 bottom
C501  SCD1U16V2KX-3DLGP  [C402H22]  56.26 44.66 0 top
C801  SC1U6D3V1MX-GP  [C0201H14]  109.33 100.06 270 top
C802  SC1U6D3V1MX-GP  [C0201H14]  67.01 98.73 270 bottom
C803  SC1U6D3V1MX-GP  [C0201H14]  108.31 90.85 225 top
C804  SC1U6D3V1MX-GP  [C0201H14]  54.75 46.39 225 top
C805  SCD1U16V2KX-3DLGP  [C402H22]  111.41 104.88 270 top
C806  SC1U6D3V1MX-GP  [C0201H14]  110.21 117.25 270 top
C807  SC22U6D3V3MX-1-DL-GP  [C603H40]  110.21 118.2 270 top
C1102  SC1U6D3V1MX-GP  [C0201H14]  76.66 95.89 0 top
C1103  SC1U6D3V1MX-GP  [C0201H14]  83.42 104.65 270 top
C1104  SC1U6D3V1MX-GP  [C0201H14]  77.77 103.68 0 top
C1105  SC1U6D3V1MX-GP  [C0201H14]  77.47 95.89 0 top
C1106  SC1U6D3V1MX-GP  [C0201H14]  82.2 116.56 90 top
C1107  SC1U6D3V1MX-GP  [C0201H14]  83.43 104.12 270 top
C1108  SC1U6D3V1MX-GP  [C0201H14]  105.44 91.14 270 top
C1109  SC1U6D3V1MX-GP  [C0201H14]  108.92 96.41 270 top
C1110  SC1U6D3V1MX-GP  [C0201H14]  95.47 90.87 0 top
C1111  SC1U6D3V1MX-GP  [C0201H14]  94.71 90.87 0 top
C1112  SC22U6D3V3MX-1-DL-GP  [C603H40]  112.3 121.08 270 top
C1113  SC22U6D3V3MX-1-DL-GP  [C603H40]  133.26 92.64 0 bottom
C1114  SC1U6D3V1MX-GP  [C0201H14]  114.07 95.49 90 top
C1115  SC22U6D3V3MX-1-DL-GP  [C603H40]  108.87 94.18 270 top
C1116  SC1U6D3V1MX-GP  [C0201H14]  111 95.42 270 top
C1117  SC1U6D3V1MX-GP  [C0201H14]  121.72 118.87 0 bottom
C1118  SC22U6D3V3MX-1-DL-GP  [C603H40]  112.27 122.4 270 top
C1119  SC1U6D3V1MX-GP  [C0201H14]  123.78 127.38 90 top
C1120  SC10U6D3V3MX-DL-GP  [C603H36]  112.33 125.34 270 top
C1121  SC1U6D3V1MX-GP  [C0201H14]  108.98 98.3 270 top
C1122  SC22U6D3V3MX-1-DL-GP  [C603H40]  122.16 89.52 180 top
C1123  SC10U6D3V3MX-DL-GP  [C603H36]  134.43 92.64 0 bottom
C1128  SC22U6D3V3MX-1-DL-GP  [C603H40]  108.87 95.38 270 top
C1129  SC22U6D3V3MX-1-DL-GP  [C603H40]  122.41 117.63 90 top
C1130  SC22U6D3V3MX-1-DL-GP  [C603H40]  84.51 71.05 270 top
C1131  SC22U6D3V3MX-1-DL-GP  [C603H40]  85.47 91.01 270 top
C1132  SC22U6D3V3MX-1-DL-GP  [C603H40]  88.47 91.62 180 top
C1133  SC22U6D3V3MX-1-DL-GP  [C603H40]  120.6 119.03 0 bottom
C1134  SC22U6D3V3MX-1-DL-GP  [C603H40]  111.99 115.55 180 bottom
C1135  SC22U6D3V3MX-1-DL-GP  [C603H40]  110.77 115.55 180 bottom
C1136  SC10U6D3V3MX-DL-GP  [C603H36]  98.45 73.03 135 top
C1137  SC10U6D3V3MX-DL-GP  [C603H36]  85.47 92.2 270 top
C1138  SC10U6D3V3MX-DL-GP  [C603H36]  84.51 73.43 270 top
C1139  SCD1U16V2KX-3DLGP  [C402H22]  149.23 54.28 135 top
C1140  SCD1U16V2KX-3DLGP  [C402H22]  81.74 48.01 180 top
C1141  SCD1U16V2KX-3DLGP  [C402H22]  65.03 50.34 180 top
C1142  SCD1U16V2KX-3DLGP  [C402H22]  123.8 49.96 0 top
C1202  SC10U6D3V3MX-GP  [C603H38]  84.51 74.63 270 top
C1203  SC10U6D3V3MX-GP  [C603H38]  84.51 75.82 270 top
C1204  SC10U6D3V3MX-GP  [C603H38]  100.13 71.35 135 top
C1205  SC10U6D3V3MX-GP  [C603H38]  99.29 72.19 135 top
C1206  SC10U6D3V3MX-GP  [C603H38]  89.67 91.62 180 top
C1207  SC1U6D3V1MX-GP  [C0201H14]  96.88 50.93 270 top
C1208  SC10U6D3V3MX-GP  [C603H38]  73.66 40 180 bottom
C1209  SC10U6D3V3MX-GP  [C603H38]  100.97 70.51 135 top
C1210  SC10U6D3V3MX-GP  [C603H38]  84.51 69.85 270 top
C1214  SC1U6D3V1MX-GP  [C0201H14]  96.53 53.33 270 top
C1215  SC1U6D3V1MX-GP  [C0201H14]  140.71 43.23 0 top
C1216  SC1U6D3V1MX-GP  [C0201H14]  141.48 43.23 0 top
C1217  SC1U6D3V1MX-GP  [C0201H14]  151.26 51.31 135 top
C1218  SC1U6D3V1MX-GP  [C0201H14]  162.84 46.69 180 top
C1219  SC1U6D3V1MX-GP  [C0201H14]  92.97 58.52 315 top
C1220  SC1U6D3V1MX-GP  [C0201H14]  152.43 50.17 135 top
C1221  SC1U6D3V1MX-GP  [C0201H14]  142.37 43.23 0 top
C1222  SCD022U16V2KX-3GP  [C402H22]  70.84 41.12 180 top
C1223  SC4D7U6D3V3KX-GP  [C603H36]  97.66 40.29 270 bottom
C1225  SC1U6D3V1MX-GP  [C0201H14]  93.48 42.32 270 top
C1226  SC1U6D3V1MX-GP  [C0201H14]  93.48 41.5 270 top
C1227  SC4D7U6D3V3KX-GP  [C603H36]  95.27 40.28 90 bottom
C1228  SCD1U16V2KX-L-GP  [C402H22]  96.4 48.13 270 top
C1229  SCD1U16V2KX-3DLGP  [C402H22]  73.08 45.31 90 top
C1231  SC10U6D3V2MX-2-GP  [C402-TO0D2H28]  96.78 51.77 270 top
C1301  SCD1U16V2KX-3DLGP  [C402H22]  149.25 43.71 90 top
C1303  SC10U6D3V3MX-GP  [C603H38]  87.28 91.62 180 top
C1304  SC10U6D3V2MX-2-GP  [C402-TO0D2H28]  59.13 50.36 180 top
C1305  SC10U6D3V3MX-GP  [C603H38]  72.47 40 180 bottom
C1306  SC10U6D3V3MX-GP  [C603H38]  84.51 72.24 270 top
C1307  SC10U6D3V2MX-2-GP  [C402-TO0D2H28]  149.86 53.51 135 top
C1308  SC10U6D3V3MX-GP  [C603H38]  71.25 40.01 180 bottom
C1309  SC10U6D3V2MX-2-GP  [C402-TO0D2H28]  150.63 52.76 135 top
C1310  SC10U6D3V3MX-GP  [C603H38]  64.93 40.45 90 bottom
C1311  SC10U6D3V2MX-2-GP  [C402-TO0D2H28]  170.77 51.81 315 top
C1313  SC1U6D3V1MX-GP  [C0201H14]  96.88 50.17 270 top
C1315  SC1U6D3V1MX-GP  [C0201H14]  72.51 50.11 135 top
C1316  SC1U6D3V1MX-GP  [C0201H14]  60.84 50.34 180 top
C1317  SC1U6D3V1MX-GP  [C0201H14]  43.61 45.91 180 top
C1318  SC1U6D3V1MX-GP  [C0201H14]  67.8 50.37 180 top
C1319  SC1U6D3V1MX-GP  [C0201H14]  53.56 43.91 270 top
C1320  SC1U6D3V1MX-GP  [C0201H14]  76.43 45.92 180 top
C1321  SC1U6D3V1MX-GP  [C0201H14]  63.4 50.37 180 top
C1322  SC1U6D3V1MX-GP  [C0201H14]  69.35 49.58 135 top
C1323  SCD022U16V2KX-3GP  [C402H22]  144.22 42.75 270 top
C1324  SC10U6D3V2MX-2-GP  [C402-TO0D2H28]  93.45 39.65 270 top
C1325  SC10U6D3V2MX-2-GP  [C402-TO0D2H28]  93.45 40.59 270 top
C1326  SC1U6D3V1MX-GP  [C0201H14]  171.57 44.07 180 top
C1327  SC1U6D3V1MX-GP  [C0201H14]  172.12 44.07 180 top
C1328  SCD1U16V2KX-L-GP  [C402H22]  171.37 51.19 315 top
C1329  SC2D2U6D3V2MX-DL-GP  [C402H22]  171.92 50.63 315 top
C1701  SC220P50V2KX-3DLGP  [C402H22]  154.03 139.63 0 bottom
C1702  SCD22U10V2KX-1GP  [C402H22]  137.66 129.06 270 bottom
C1703  SCD22U10V2KX-1GP  [C402H22]  61.5 127.99 270 bottom
C1711  SCD1U16V2KX-3DLGP  [C402H22]  104.3 115.65 90 bottom
C1803  SC12P50V2JN-DL-GP  [C402H22]  135.13 78.54 270 top
C1804  SC12P50V2JN-DL-GP  [C402H22]  137.16 78.54 90 top
C1805  SC1U6D3V1MX-GP  [C0201H14]  139.47 89.07 0 top
C1806  SC1U6D3V1MX-GP  [C0201H14]  137.93 90.48 180 top
C1807  SC15P50V2JN-DL-GP  [C402H22]  133 115.95 90 bottom
C1808  SC15P50V2JN-DL-GP  [C402H22]  129.9 115.95 270 bottom
C1809  SC2D2P50V2CC-DLGP  [C402H22]  136.25 118.49 180 bottom
C2201  SCD1U16V2KX-3DLGP  [C402H22]  109.32 93.19 270 top
C2202  SC1U6D3V1MX-GP  [C0201H14]  130.31 90.86 180 bottom
C2203  SC1U6D3V1MX-GP  [C0201H14]  128.75 90.86 180 bottom
C2204  SC1U6D3V1MX-GP  [C0201H14]  127.17 90.86 180 bottom
C2205  SC1U6D3V1MX-GP  [C0201H14]  127.96 90.86 180 bottom
C2206  SCD1U16V2KX-3DLGP  [C402H22]  115.88 91.87 0 top
C2207  SCD1U16V2KX-3DLGP  [C402H22]  129.51 90.86 180 bottom
C2208  SC22U6D3V3MX-1-DL-GP  [C603H40]  111.1 116.26 270 top
C2209  SC1U6D3V1MX-GP  [C0201H14]  111.29 115.22 270 top
C2210  SC1U6D3V1MX-GP  [C0201H14]  117.52 89.74 180 top
C2211  SC1U6D3V1MX-GP  [C0201H14]  135.79 93.35 180 top
C2212  SC1U6D3V1MX-GP  [C0201H14]  123.78 128.2 90 top
C2213  SC1U6D3V1MX-GP  [C0201H14]  112.06 93.01 90 top
C2214  SC1U6D3V1MX-GP  [C0201H14]  122.35 118.63 90 top
C2215  SC1U6D3V1MX-GP  [C0201H14]  112.23 118.56 270 top
C2216  SC1U6D3V1MX-GP  [C0201H14]  112.23 119.32 270 top
C2217  SC1U6D3V1MX-GP  [C0201H14]  112.23 120.08 270 top
C2218  SC4D7U6D3V3KX-DLGP  [C603H36]  123.37 91.39 0 top
C2219  SC1U6D3V1MX-GP  [C0201H14]  123.09 102.87 270 top
C2220  SC22U6D3V3MX-1-DL-GP  [C603H40]  112.17 98.3 270 top
C2221  SCD1U16V2KX-3DLGP  [C402H22]  138.31 88.77 180 top
C2222  SC1U6D3V1MX-GP  [C0201H14]  109.16 91.67 315 top
C2223  SC1U6D3V1MX-GP  [C0201H14]  126.06 117.38 180 top
C2224  SC1U6D3V1MX-GP  [C0201H14]  141.38 88.16 45 bottom
C2225  SC1U6D3V1MX-GP  [C0201H14]  116.52 91.65 0 top
C2226  SC1U6D3V1MX-GP  [C0201H14]  113.09 93.01 270 top
C2227  SC1U6D3V1MX-GP  [C0201H14]  117.04 91.65 0 top
C2228  SC1U6D3V1MX-GP  [C0201H14]  111.76 93.52 90 top
C2229  SC1U6D3V1MX-GP  [C0201H14]  109.54 91.3 315 top
C2230  SC1U6D3V1MX-GP  [C0201H14]  110.45 90.91 315 top
C2231  SC22U6D3V3MX-1-DL-GP  [C603H40]  124.56 102.01 90 top
C2405  SC100P50V2JN-3GP  [C402H22]  41.55 72.9 180 top
C2406  SCD1U16V2KX-3DLGP  [C402H22]  40.78 72.84 180 top
C2407  SCD1U16V2KX-3DLGP  [C402H22]  39.14 77.62 0 top
C2408  SCD1U16V2KX-3DLGP  [C402H22]  33.07 76.84 0 top
C2409  SCD01U25V2KX-3DLGP  [C402H22]  23.35 63.98 0 bottom
C2410  SCD1U16V2KX-3DLGP  [C402H22]  38.06 57.31 270 top
C2411  SCD1U16V2KX-3DLGP  [C402H22]  30.2 76.28 90 top
C2412  SCD1U16V2KX-3DLGP  [C402H22]  20.53 71.16 270 top
C2413  SCD1U16V2KX-3DLGP  [C402H22]  41.05 67.49 90 top
C2414  SCD1U16V2KX-3DLGP  [C402H22]  34.14 75.29 270 top
C2416  SCD1U16V2KX-3DLGP  [C402H22]  42.05 77.65 270 top
C2418  SC1U6D3V1MX-GP  [C0201H14]  23.75 65.89 270 bottom
C2420  SCD1U16V2KX-3DLGP  [C402H22]  29.02 56.1 0 top
C2421  SCD1U16V2KX-3DLGP  [C402H22]  41.16 68.99 270 top
C2422  SCD1U16V2KX-3DLGP  [C402H22]  30.2 77.09 90 top
C2423  SCD1U16V2KX-3DLGP  [C402H22]  33.4 56.06 0 top
C2424  SC18P50V2JN-1DLGP  [C402H22]  26.49 75.6 270 top
C2425  SC18P50V2JN-1DLGP  [C402H22]  28.2 75.57 270 top
C2426  SC2D2U10V3KX-1DLGP-U  [C603H36]  23.78 77.42 180 top
C2428  SCD1U16V2KX-3DLGP  [C402H22]  23.85 72.19 90 bottom
C2429  SCD1U16V2KX-3DLGP  [C402H22]  23.75 65.13 270 bottom
C2431  SC2200P50V2KX-2GP  [C402H22]  31.35 76.79 180 top
C2432  SCD1U16V2KX-3DLGP  [C402H22]  47.74 67.75 45 top
C2435  SC2200P50V2KX-2GP  [C402H22]  36.58 77.19 90 top
C2501  SC10U6D3V3MX-DL-GP  [C603H36]  157.18 96.22 270 bottom
C2502  SCD1U16V2KX-3DLGP  [C402H22]  156.47 94.44 270 bottom
C2503  SCD47U25V3KX-1GP  [C603H36]  155.71 79.25 0 bottom
C2517  SCD022U16V2KX-3DLGP  [C402H22]  163.93 82.88 0 bottom
C2525  SC1U6D3V1MX-GP  [C0201H14]  159.31 96.46 315 bottom
C2601  SC10U6D3V3MX-DL-GP  [C603H36]  132.69 121.67 90 top
C2602  SCD1U16V2KX-3GP  [C402H22]  132.62 122.68 90 top
C2603  SC2200P50V2KX-2DLGP  [C402H22]  158.07 90.43 90 bottom
C2604  SC4D7U6D3V3KX-DLGP  [C603H36]  162.79 92.18 180 bottom
C2605  SCD1U25V2KX-1-DL-GP  [C402H22]  158.07 89.59 90 bottom
C2606  SC470P50V3JN-2GP  [C603H36]  134.37 124.89 180 top
C2607  SC2200P50V2KX-2DLGP  [C402H22]  133.38 124.94 180 top
C2610  SCD1U16V2KX-3DLGP  [C402H22]  140.75 116.84 90 bottom
C2612  SCD1U16V2KX-3GP  [C402H22]  21.62 66.45 90 top
C2613  SC100P50V2JN-3DLGP  [C402H22]  56.76 91.29 180 bottom
C2614  SCD1U16V2KX-3DLGP  [C402H22]  156.13 138.31 0 bottom
C2702  SC2D2U6D3V2MX-DL-GP  [C402H22]  23.8 9.27 180 top
C2703  SC10U6D3V2MX-2-GP  [C402-TO0D2H28]  22.94 9.91 0 top
C2704  SCD1U16V2KX-3GP  [C402H22]  30.53 7.82 270 top
C2705  SC2D2U10V3KX-1DLGP-U  [C603H36]  30.94 8.82 90 top
C2706  SCD1U16V2KX-3GP  [C402H22]  22.72 11.53 180 top
C2707  SC10U10V3MX-1-GP  [C603H36]  20.53 11.43 270 top
C2708  SC2D2U10V3KX-1DLGP-U  [C603H36]  32.79 7.7 180 top
C2709  SC2D2U10V3KX-1DLGP-U  [C603H36]  29.16 7.88 0 top
C2710  SC10U6D3V2MX-2-GP  [C402-TO0D2H28]  33.2 11.28 270 top
C2711  SC10U6D3V2MX-2-GP  [C402-TO0D2H28]  33.86 10.09 90 top
C2713  SC10U10V3MX-GP-U  [C603H38]  33.12 13.84 180 top
C2714  SCD1U16V2KX-3GP  [C402H22]  32.13 13.82 180 top
C2715  SC10U6D3V2MX-2-GP  [C402-TO0D2H28]  19 15.8 270 top
C2717  SC10U10V3MX-GP-U  [C603H38]  34.37 15.77 0 top
C2718  SCD1U16V2KX-3GP  [C402H22]  32.13 15.32 0 top
C2720  SC10U6D3V3MX-GP  [C603H38]  29.67 19.38 90 top
C2721  SCD1U16V2KX-3GP  [C402H22]  30.25 17.48 90 top
C2722  SC10U6D3V3MX-GP  [C603H38]  25.58 19.13 180 top
C2723  SCD1U16V2KX-3GP  [C402H22]  30.23 18.26 90 top
C2735  SCD1U16V2KX-3DLGP  [C402H22]  22.62 18.61 0 top
C2736  SC10U6D3V3MX-GP  [C603H38]  29.67 21.74 90 top
C2740  SC2D2U10V3KX-L-GP  [C603H36]  29.67 20.56 90 top
C2741  SCD1U16V2KX-3GP  [C402H22]  23.75 18.72 180 top
C2902  SC10U6D3V3MX-GP  [C603H38]  19.72 18.35 180 top
C2907  SC4D7U6D3V3KX-DLGP  [C603H36]  20.29 12.62 270 top
C2908  SC4D7U6D3V3KX-DLGP  [C603H36]  20.29 13.81 270 top
C3102  SCD1U16V2KX-3DLGP  [C402H22]  48.35 79.65 180 top
C3103  SCD1U16V2KX-3DLGP  [C402H22]  46.15 81.36 0 bottom
C3104  SCD1U16V2KX-3DLGP  [C402H22]  46.28 79.68 180 top
C3107  SCD1U16V2KX-3DLGP  [C402H22]  49.13 79.65 180 top
C3108  SCD1U16V2KX-3DLGP  [C402H22]  44.45 81.69 270 bottom
C3109  SCD1U16V2KX-3DLGP  [C402H22]  47.04 79.68 180 top
C3110  SC4D7U6D3V3KX-DLGP  [C603H36]  45.25 84.98 180 bottom
C3112  SCD1U16V2KX-3DLGP  [C402H22]  44.3 82.58 270 bottom
C3115  SCD1U16V2KX-3DLGP  [C402H22]  44.3 83.38 270 bottom
C3116  SC15P50V2JN-DL-GP  [C402H22]  44.2 87.05 270 top
C3117  SCD1U16V2KX-3DLGP  [C402H22]  48.14 84.68 90 bottom
C3118  SCD1U16V2KX-3DLGP  [C402H22]  48.14 85.47 90 bottom
C3119  SCD1U16V2KX-3DLGP  [C402H22]  46.61 85.57 270 bottom
C3120  SCD1U16V2KX-3DLGP  [C402H22]  48.13 83.1 90 bottom
C3121  SCD1U16V2KX-3DLGP  [C402H22]  44.28 84.76 180 bottom
C3122  SC1U6D3V1MX-GP  [C0201H14]  47.6 86.72 180 bottom
C3123  SCD1U16V2KX-3DLGP  [C402H22]  44.45 80.9 270 bottom
C3124  SC4D7U6D3V3KX-DLGP  [C603H36]  47.15 81.48 0 bottom
C3125  SC15P50V2JN-DL-GP  [C402H22]  46.96 86.99 90 top
C3126  SC1U6D3V1MX-GP  [C0201H14]  48.13 83.89 90 bottom
C3202  SC100P3KV8JN-2-GP  [C1808H56]  24.75 84.05 90 bottom
C3203  SCD01U50V2KX-1DLGP  [C402H22]  39.12 84.25 0 bottom
C3507  SC1U10V2KX-1DLGP  [C402H22]  17.43 34.04 90 bottom
C3516  SCD1U16V2KX-3DLGP  [C402H22]  17.35 33.4 0 top
C3517  SC1U10V2KX-1DLGP  [C402H22]  16.56 33.4 0 top
C3518  SC22U6D3V3MX-1-DL-GP  [C603H40]  17.45 37.44 270 bottom
C3519  SC22U6D3V3MX-1-DL-GP  [C603H40]  16.79 35.64 180 bottom
C3520  SCD1U16V2KX-3DLGP  [C402H22]  20.62 56.87 180 bottom
C3521  SCD1U16V2KX-3DLGP  [C402H22]  21.41 56.87 180 bottom
C3522  SCD1U16V2KX-3DLGP  [C402H22]  21.85 44.9 90 bottom
C3523  SCD1U16V2KX-3DLGP  [C402H22]  21.85 44.12 90 bottom
C3524  SCD1U16V2KX-3DLGP  [C402H22]  18.98 56.49 180 bottom
C3525  SC1U10V2KX-1DLGP  [C402H22]  16.56 56.99 0 top
C3526  SC22U6D3V3MX-1-DL-GP  [C603H40]  17.99 56.44 180 bottom
C3527  SC22U6D3V3MX-1-DL-GP  [C603H40]  16.78 56.43 180 bottom
C3602  SCD1U16V2KX-3DLGP  [C402H22]  26.37 51.16 0 top
C4001  SC470P50V2KX-3GP  [C402H22]  55.81 128.63 90 bottom
C4002  SC470P50V2KX-3GP  [C402H22]  61.6 39.79 180 top
C4004  SC10U25V5KX-DL-GP  [C805H58]  53.61 129.28 90 bottom
C4005  SC10U10V3MX-GP-U  [C603H38]  18.07 97.42 90 top
C4006  SC10U6D3V3MX-DL-GP  [C603H36]  108.77 97.38 270 top
C4007  SCD1U16V2KX-3DLGP  [C402H22]  67.01 99.49 270 bottom
C4008  SC10U6D3V3MX-DL-GP  [C603H36]  139.86 82.14 90 top
C4009  SC10U6D3V3MX-DL-GP  [C603H36]  139.31 117.64 180 bottom
C4010  SCD1U16V2KX-3DLGP  [C402H22]  135.95 84.05 180 top
C4011  SC470P50V2KX-3GP  [C402H22]  62.39 39.77 180 top
C4012  SC10U6D3V3MX-DL-GP  [C603H36]  113.26 125.5 180 bottom
C4013  SC10U6D3V3MX-DL-GP  [C603H36]  112.32 126.54 270 top
C4014  SC10U25V5KX-DL-GP  [C805H58]  47.16 79.43 270 bottom
C4015  SC10U6D3V3MX-DL-GP  [C603H36]  63.82 39.26 270 bottom
C4017  SC470P50V2KX-3GP  [C402H22]  55.73 127.33 90 bottom
C4031  SC1U10V2KX-1DLGP  [C402H22]  120.22 127.74 270 bottom
C4032  SC1U10V2KX-1DLGP  [C402H22]  126.32 116.18 0 bottom
C4033  SCD1U25V2KX-1-DL-GP  [C402H22]  125.15 114.91 180 bottom
C4034  SCD1U25V2KX-1-DL-GP  [C402H22]  120.22 126.9 270 bottom
C4035  SC22U6D3V3MX-1-DL-GP  [C603H40]  123.85 129.21 90 top
C4036  SC22U6D3V3MX-1-DL-GP  [C603H40]  122.71 119.03 0 bottom
C4041  SC1U10V2KX-1DLGP  [C402H22]  142.86 84.99 90 top
C4043  SC1U6D3V1MX-GP  [C0201H14]  133.43 79.1 315 bottom
C4301  SC1U50V3KX-1-GP  [C603H36]  26.2 128.87 0 top
C4302  SC1U50V3KX-1-GP  [C603H36]  25.96 123.78 270 top
C4303  SCD01U50V2KX-1DLGP  [C402H22]  32.77 133.33 180 top
C4304  SCD01U50V2KX-1DLGP  [C402H22]  31.24 133.33 180 top
C4305  SCD01U50V2KX-1DLGP  [C402H22]  32.01 133.33 180 top
C4306  SC10U25V5KX-DL-GP  [C805H58]  29.47 133.43 270 top
C4343  SC1500P50V2KX-2-DL-GP  [C402H22]  34.78 126.42 90 top
C4344  SC1KP50V2KX-1DLGP  [C402H22]  41.82 116.48 180 top
C5503  SC4D7U6D3V2MX-1-GP  [C402H22]  216.28 47.83 180 top
C5504  SC4D7U6D3V2MX-1-GP  [C402H22]  223.75 42.55 180 top
C5505  SC10U6D3V2MX-2-GP  [C402-TO0D2H28]  216.03 46.12 270 top
C5512  SCD1U25V2KX-GP  [C402H22]  216.73 36.84 270 top
C5513  SC1KP50V2KX-1DLGP  [C402H22]  216.61 37.62 270 top
C5514  SC10U25V3MX-3-GP  [C603H40]  215.36 42.7 0 bottom
C5516  SCD1U25V2KX-GP  [C402H22]  221.62 42.55 180 top
C5517  SC10U6D3V2MX-2-GP  [C402-TO0D2H28]  222.46 42.44 180 top
C5520  SC4D7U6D3V2MX-1-GP  [C402H22]  209.61 45.84 180 top
C5521  SCD1U16V2KX-3GP  [C402H22]  215.16 54.95 270 bottom
C5522  SCD1U16V2KX-3GP  [C402H22]  215.16 52.66 270 bottom
C5523  SCD1U16V2KX-3GP  [C402H22]  215.16 51.9 270 bottom
C5524  SCD1U16V2KX-3GP  [C402H22]  215.16 54.18 270 bottom
C5525  SCD1U16V2KX-3GP  [C402H22]  215.16 53.42 270 bottom
C5526  SCD1U16V2KX-3GP  [C402H22]  215.16 55.71 270 bottom
C5528  SCD1U25V2KX-GP  [C402H22]  146.39 131.33 180 top
C5529  SCD1U16V2KX-3DLGP  [C402H22]  147.03 133.83 270 top
C5530  SCD1U16V2KX-3DLGP  [C402H22]  149.95 133.85 0 top
C5531  SC2200P50V2KX-2DLGP  [C402H22]  145.17 134.05 180 top
C5535  SC2200P50V2KX-2DLGP  [C402H22]  149.21 131.79 270 top
C5536  SC1U6D3V1MX-GP  [C0201H14]  216.64 38.3 270 top
C5538  SCD1U16V2KX-3DLGP  [C402H22]  216.64 39.07 270 top
C5539  SC470P50V2KX-3GP  [C402H22]  212.63 43.08 270 top
C5540  SC470P50V2KX-3GP  [C402H22]  212.63 43.84 270 top
C5541  SC1U6D3V1MX-GP  [C0201H14]  220.93 40.92 180 top
C5599  SC4D7U6D3V2MX-1-GP  [C402H22]  217.47 41.23 270 top
C5724  SCD01U50V2KX-1GP  [C402H22]  21.8 100.81 0 bottom
C5736  SCD1U16V2KX-3DLGP  [C402H22]  16.92 101.3 270 top
C5777  SCD1U16V2KX-3GP  [C402H22]  24.49 95.02 90 bottom
C5778  SCD1U16V2KX-3GP  [C402H22]  24.49 94.24 90 bottom
C5779  SCD1U16V2KX-3GP  [C402H22]  23.8 97.11 90 bottom
C5780  SCD1U16V2KX-3GP  [C402H22]  23.8 96.32 90 bottom
C5781  SCD1U16V2KX-3GP  [C402H22]  24.56 99.11 90 bottom
C5782  SCD1U16V2KX-3GP  [C402H22]  24.56 98.32 90 bottom
C5783  SCD1U16V2KX-3GP  [C402H22]  25.17 101.22 90 bottom
C5784  SCD1U16V2KX-3GP  [C402H22]  25.17 100.43 90 bottom
C5801  SCD1U16V2KX-3DLGP  [C402H22]  49.81 111.64 180 top
C5802  SCD1U16V2KX-3DLGP  [C402H22]  50.57 111.64 180 top
C5803  SCD1U16V2KX-3DLGP  [C402H22]  46.57 111.63 180 top
C5804  SCD1U16V2KX-3DLGP  [C402H22]  47.33 111.63 180 top
C5805  SCD1U16V2KX-3DLGP  [C402H22]  52.17 111.69 180 top
C5806  SCD1U16V2KX-3DLGP  [C402H22]  52.94 111.69 180 top
C5807  SCD1U16V2KX-3DLGP  [C402H22]  53.7 111.69 180 top
C5808  SCD1U16V2KX-3DLGP  [C402H22]  54.46 111.69 180 top
C5809  SCD1U16V2KX-3DLGP  [C402H22]  52.6 117.87 180 bottom
C5810  SCD01U25V2KX-3DLGP  [C402H22]  45.29 119.92 180 top
C5811  SCD1U16V2KX-3DLGP  [C402H22]  43.93 115.42 270 top
C5812  SCD1U16V2KX-3DLGP  [C402H22]  56.34 120.8 180 top
C5813  SCD1U16V2KX-3DLGP  [C402H22]  56.9 114.75 90 top
C5854  SCD1U16V2KX-3DLGP  [C402H22]  57.89 116.31 270 top
C5862  SCD1U16V2KX-3DLGP  [C402H22]  57.89 115.55 270 top
C5863  SC2D2U10V2KX-GP  [C402H22]  53.72 113.71 180 bottom
C6007  SCD1U16V2KX-3DLGP  [C402H22]  161.33 37.84 90 top
C6008  SC10U10V2MX-DL-GP-U  [C402-TO0D2H28]  161.44 38.73 90 top
C6010  SCD01U25V2KX-3DLGP  [C402H22]  189.11 38.79 270 top
C6011  SCD01U25V2KX-3DLGP  [C402H22]  189.11 39.55 270 top
C6013  SCD01U25V2KX-3DLGP  [C402H22]  192.48 41.61 180 top
C6014  SCD01U25V2KX-3DLGP  [C402H22]  191.72 41.61 180 top
C6018  SC10U10V2MX-DL-GP-U  [C402-TO0D2H28]  189.64 33.68 0 top
C6019  SCD1U16V2KX-3DLGP  [C402H22]  188.78 33.73 0 top
C6028  SCD01U25V2KX-3DLGP  [C402H22]  166.01 36.6 180 top
C6029  SCD01U25V2KX-3DLGP  [C402H22]  165.23 36.6 180 top
C6030  SCD01U25V2KX-3DLGP  [C402H22]  162.97 36.6 180 top
C6031  SCD01U25V2KX-3DLGP  [C402H22]  162.2 36.6 180 top
C6102  SC4D7U6D3V3KX-L-GP  [C603H36]  53.19 106.58 270 top
C6104  SCD1U16V2KX-3DLGP  [C402H22]  50.16 105.07 180 top
C6105  SC10U6D3V3MX-DL-GP  [C603H36]  51.29 105.16 180 top
C6106  SCD1U25V2KX-1-DL-GP  [C402H22]  49.39 105.07 180 top
C6107  SCD1U16V2KX-3DLGP  [C402H22]  40.07 94.95 180 bottom
C6108  SCD1U16V2KX-3DLGP  [C402H22]  39.29 94.95 180 bottom
C6201  SCD1U16V2KX-3DLGP  [C402H22]  214.96 61.13 90 top
C6202  SCD1U16V2KX-3DLGP  [C402H22]  214.96 61.89 90 top
C6302  SCD22U10V2KX-2-GP  [C402H22]  23.85 35.23 0 bottom
C6303  SCD22U10V2KX-2-GP  [C402H22]  24.64 35.23 0 bottom
C6304  SC33P50V2JN-3DLGP  [C402H22]  20.4 21.63 90 top
C6305  SC33P50V2JN-3DLGP  [C402H22]  17.02 25.71 270 top
C6306  SCD047U25V2KX-4-GP  [C402H22]  17.02 24.18 270 top
C6307  SCD1U16V2KX-3DLGP  [C402H22]  17.02 23.42 270 top
C6308  SCD047U25V2KX-4-GP  [C402H22]  17.02 24.94 270 top
C6311  SCD22U10V2KX-2-GP  [C402H22]  26.54 37.27 0 bottom
C6312  SCD22U10V2KX-2-GP  [C402H22]  27.3 37.27 0 bottom
C6313  SCD22U10V2KX-2-GP  [C402H22]  29.56 37.25 0 bottom
C6314  SCD22U10V2KX-2-GP  [C402H22]  30.32 37.25 0 bottom
C6315  SCD22U10V2KX-2-GP  [C402H22]  32.61 37.22 0 bottom
C6316  SCD22U10V2KX-2-GP  [C402H22]  33.37 37.22 0 bottom
C6317  SC10U6D3V3MX-DL-GP  [C603H36]  40.21 28.49 180 bottom
